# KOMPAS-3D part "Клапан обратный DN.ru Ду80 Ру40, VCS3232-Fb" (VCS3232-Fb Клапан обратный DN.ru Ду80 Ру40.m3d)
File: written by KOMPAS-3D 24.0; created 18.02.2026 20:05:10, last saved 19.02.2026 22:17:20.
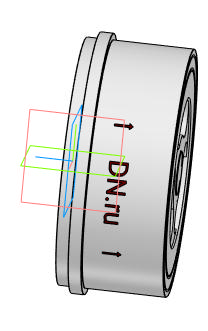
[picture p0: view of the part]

Document properties: Автор: R2D2; Полное имя файла: D:\Работа\Клапаны обратные\VCS3232-Fb Клапан обратный DN.ru Ду15-100\DN80\VCS3232-Fb Клапан обратный DN.ru Ду80 Ру40.m3d

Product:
- Body: Тело 1  | qty 1
    Масса: 2.07873
- Body: Тело 2  | qty 1
    Масса: 0.88072
- Part/product: Клапан обратный DN.ru Ду80 Ру40  | designation VCS3232-Fb
    Масса: 2.18
    Раздел спецификации: Прочие изделия
    Примечание: D100-03712
    additional columns: 1; D100-03712

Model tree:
1. Операция без истории:1
2. Операция без истории:2

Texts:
  Точка начала. Х
  Точка начала. Y
  Точка начала. Z
  VCS3232-Fb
